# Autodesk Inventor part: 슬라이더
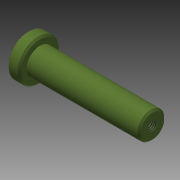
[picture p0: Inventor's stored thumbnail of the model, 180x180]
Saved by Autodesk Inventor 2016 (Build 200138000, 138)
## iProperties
Created: 2011-04
Part Number: 슬라이더
Document SubType Name: Modeling
Density: 1 g/cm^3
Material: 일반
Appearance: 올리브 녹색
Author: pww
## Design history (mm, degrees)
sketch "스케치1"
  geometry: L1 (-7, 0)-(63, 0); L2 (63, 0)-(63, 7.5); L3 (63, 7.5)-(0, 7.5); L4 (-7, 0)-(-7, 11.5); L5 (-7, 11.5)-(0, 11.5); L6 (0, 11.5)-(0, 7.5); 1 further point
  constraints: 12 end point, 3 perpendicular, 2 horizontal, 2 point on line, 1 parallel
  dimensions: "d1" = 70 distance of L1.start L1.end; "d19" = 15 diameter of L3 L1; "d20" = 7 distance of L4.end L5.end; "d21" = 23 diameter of L5 L1
revolve "회전1" stored, may be unused: angle "d4" = 90 deg
chamfer "모따기1" distance "d16" = 1; stored, may be unused: second distance "d17" = 2, angle "d18" = 45 deg
hole "구멍2" diameter "d24" = 4.917; stored, may be unused: countersink angle "d28" = 90 deg, drill point angle "d30" = 118 deg; dims "d22" = 10, "d23" = 10, "d25" = 10, "d26" = 4, "d27" = 2, "d29" = 13
node "솔리드1"
